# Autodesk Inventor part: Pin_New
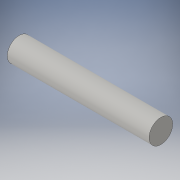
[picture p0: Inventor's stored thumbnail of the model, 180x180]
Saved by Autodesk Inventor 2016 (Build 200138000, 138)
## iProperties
Created: 2016-03
Part Number: Pin_New
Material: Generic
Document SubType Name: Modeling
Designer: fisher
Density: 1 g/cm^3
Appearance: Default
Author: fisher
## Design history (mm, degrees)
sketch "Sketch1"
  geometry: C1 r 3.175 at (0, 0); 1 further point
  constraints: 1 centre point, 1 coincident
  dimensions: "d0" = 6.35 diameter of C1
extrude "Extrusion1" new body sketch "Sketch1" distance "d1" = 38.1; taper "d2" = 0 deg
body "Solid1"
